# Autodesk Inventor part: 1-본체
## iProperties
Created: 2015-03
Part Number: 1-본체
Document SubType Name: Modeling
Designer: now102
Density: 2.71 g/cm^3
Material: 알루미늄-6061
Mass: 529.787 g
Surface Area: 369.152 cm^2
Volume: 195.493 cm^3
Author: now102
